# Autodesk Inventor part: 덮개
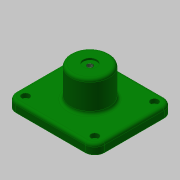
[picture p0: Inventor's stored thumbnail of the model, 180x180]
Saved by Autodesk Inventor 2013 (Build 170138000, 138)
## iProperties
Created: 2017-08
Part Number: 덮개
Material: 알루미늄 6061
Document SubType Name: Modeling
Designer: mduedu
Density: 1 g/cm^3
Author: mduedu
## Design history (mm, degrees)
sketch "스케치1"
  geometry: L1 (46, -41)-(-46, -41); L2 (-46, -41)-(-46, 41); L3 (-46, 41)-(46, 41); L4 (46, 41)-(46, -41); 1 further point
  constraints: 8 end point, 2 parallel, 1 horizontal, 1 perpendicular
  dimensions: "d0" = 92 distance of L2.end L3.end; "d2" = 82 distance of L1.end L2.end; "d3" = 41 distance from line of L3 point (0, 0) (= 0.5 x d2); "d4" = 46 distance from line of point (0, 0) L4 (= 0.5 x d0)
extrude "돌출1" new body sketch "스케치1" distance "d5" = 10; taper "d6" = 0 deg
sketch "스케치2"
  geometry: C1 r 20 at (0, 0); 1 further point
  constraints: 1 centre point, 1 coincident
  dimensions: "d55" = 40 diameter of C1
extrude "돌출2" join sketch "스케치2" distance "d9" = 32; taper "d10" = 0 deg
sketch "스케치3"
  geometry: L1 (-26, -26)-(26, -26); L2 (26, -26)-(26, 26); L3 (26, 26)-(-26, 26); L4 (-26, 26)-(-26, -26); L5 (-26, -26)-(26, 26); L6 (26, -26)-(-26, 26); 1 further point
  constraints: 12 end point, 2 midpoint, 2 parallel, 2 perpendicular, 1 horizontal
  dimensions: "d11" = 52 distance of L3.end L2.end
extrude "돌출3" join sketch "스케치3" distance "d12" = 6; taper "d13" = 0 deg
sketch "스케치4"
  geometry: L1 (-17, -17)-(17, -17); L2 (17, -17)-(17, 17); L3 (17, 17)-(-17, 17); L4 (-17, 17)-(-17, -17); L5 (-17, -17)-(17, 17); L6 (17, -17)-(-17, 17); 1 further point
  constraints: 12 end point, 2 midpoint, 2 parallel, 2 perpendicular, 1 horizontal
  dimensions: "d14" = 34 distance of L2.end L3.end
extrude "돌출4" cut sketch "스케치4" distance "d16" = 5; taper "d17" = 0 deg
sketch "스케치5"
  geometry: C1 r 9 at (0, 0); 1 further point
  constraints: 1 centre point, 1 coincident
  dimensions: "d18" = 18 diameter of C1
extrude "돌출5" cut sketch "스케치5" distance "d19" = 34; taper "d20" = 0 deg
sketch "스케치6"
  geometry: 2 further points
  constraints: 1 coincident
hole "구멍1" sketch "스케치6" at (0, 0) diameter "d21" = 5.917; stored, may be unused: countersink angle "d25" = 90 deg, drill point angle "d27" = 118 deg; dims "d22" = 6, "d23" = 14, "d24" = 2, "d26" = 8
fillet "모깎기1" dims "d36" = 10
fillet "모깎기3" dims "d38" = 3
fillet "모깎기4" dims "d39" = 3
fillet "모깎기5" dims "d40" = 3
chamfer "모따기1" distance "d41" = 1; stored, may be unused: second distance "d42" = 2, angle "d43" = 45 deg
fillet "모깎기6" dims "d44" = 3
fillet "모깎기7" dims "d45" = 3
fillet "모깎기8" dims "d46" = 3
sketch "스케치8"
  geometry: A1 r 10 centre (-36, -31) between (-46, -31) and (-36, -41) reference; A2 r 10 centre (-36, 31) between (-36, 41) and (-46, 31) reference; A3 r 10 centre (36, 31) between (46, 31) and (36, 41) reference; A4 r 10 centre (36, -31) between (36, -41) and (46, -31) reference; 5 further points
  constraints: 4 coincident
sketch "스케치9"
  geometry: 4 further points
  constraints: 4 other
hole "구멍3" sketch "스케치9" at (-36, -31), (-36, 31), (36, 31), (36, -31) diameter "d48" = 4.5; stored, may be unused: countersink angle "d52" = 90 deg, drill point angle "d54" = 0 deg; dims "d49" = 6, "d50" = 8, "d51" = 4.6, "d53" = 8
node "솔리드1"
